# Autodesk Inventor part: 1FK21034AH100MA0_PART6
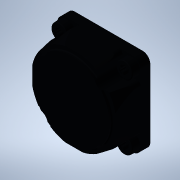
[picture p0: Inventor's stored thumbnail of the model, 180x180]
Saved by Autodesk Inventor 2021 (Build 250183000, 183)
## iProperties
Created: 2025-04
Part Number: 1FK21034AH100MA0_PART6
Material: Generic
Catalog Web Link: www.3dfindit.com
Description: -Servo synchronous motor
Document SubType Name: Modeling
Designer: psAdmin
Mass: 3.85693 g
Surface Area: 17.8404 cm^2
Volume: 3.85693 cm^3
Density: 1 g/cm^3
Appearance: PSOLRGB-48-56-69
Category: PARTsolutions
Title: 1FK21034AH100MA0_PART6
Author: Cadenas PARTsolutions
Comments: Servo synchronous motor
Sending System: PARTsolutions
Preprocessor: ST-DEVELOPER v19.3
PSOL_IDENT_0: {$CADENAS_DATA/23d-libs/siemens_ag/_cat_/39/97/1fk21034ah100ma0.prj},213 {VTYP=3D},{NB=1FK21034AH100
PSOL_IDENT_1: MA0_PART6},{LINA=1FK21034AH100MA0_PART6},{NN=1FK21034AH100MA0_PART6},{NOPRJ=TRUE},{DATE=19.08.2025 1
PSOL_IDENT_2: 4:00:33},{GEOMDATE=30.07.2025 02:02:21},{VERSION=},{LINEID=10},{WBVAR=},{WBNUMERIC=}  {NB=1FK21034AH
PSOL_IDENT_3: 100MA0_PART6},{LINA=1FK21034AH100MA0_PART6},{KT=DUMMY},{PREVIEW=../../../_pool_/d3/78/p_d211_xx_0093
PSOL_IDENT_4: 4j.png},{DESCSHORT=SIMOTICS S-1FK2 HD, SINAMICS S210 3AC 400V-480V, 1.01 Nm, 4500 rpm},{DESCLONG=SIM
PSOL_IDENT_5: OTICS S-1FK2 HD servo motor M0=1.27 Nm; PN = 0.48 kW at nN=4500 rpm (380-480 V); PN = 0.3 kW at nN=2
PSOL_IDENT_6: 500 rpm (200-240 V); with holding brake; degree of protection IP64; cylindrical shaft D14 x 30 mm; a
PSOL_IDENT_7: bsolute encoder 22-bit + 12-bit multiturn (encoder AM22DQC); with OCC interface; plug size M17, rota
PSOL_IDENT_8: table; SIMOTICS S-1FK2 servomotorfor a wide range of uses in industrial environments. SIMOTICS S‑1FK
PSOL_IDENT_9: 2 servomotors are compact synchronous motors with a high dynamic performance that set themselves apa
PSOL_IDENT_10: rt as a result of their high power density, degree of protection and overload capability. The motors
PSOL_IDENT_11: are available in two variants: as High Dynamic variant (highest dynamic performance as a result of
PSOL_IDENT_12: the low intrinsic moment of inertia for applications demanding a high dynamic performance with low m
PSOL_IDENT_13: oved masses) - and as Compact variant (precise and stable closed-loop control for medium up to large
PSOL_IDENT_14: moved masses as a result of a medium intrinsic moment of inertia). SIMOTICSS‑1FK2 servomotors fully
PSOL_IDENT_15: exploit their strengths in a system with the SINAMICSS210 frequency converter and simple connection
PSOL_IDENT_16: using the one cable connection (OCC). Advantages include the short control and positioning times, f
PSOL_IDENT_17: ast and precise correction of disturbing quantities as well as stable control with a high dynamic pe
PSOL_IDENT_18: rformance. The servo motors can be configured to address a wide range of requirements. For example w
PSOL_IDENT_19: ith and without holding brake, IP64 or IP65 degree of protection, singleturn or multiturn absolute e
PSOL_IDENT_20: ncoders - to name just a few. Further, the servomotors are available in different shaft heights exte
PSOL_IDENT_21: nding from 20 to 100. A shaft sealing ring is available to achieve an IP65 degree of protection and
PSOL_IDENT_22: for subsequent mounting at the motor or as spare part. SIMOTICS - the optimum motor for each and eve
PSOL_IDENT_23: ry motion control application.},{INTNO=195125454019},{SUPPLIERALTNO=1FK2103-4AH10-0MA0},{MANUID=1FK2
PSOL_IDENT_24: 1034AH100MA0},{MANUNAME=Siemens},{MANUTYPEDESC=SYNCHRONOUS MOTOR 1FK2 HD 1,27 NM},{AAU732=SIMOTICS},
PSOL_IDENT_25: {AAO057=S-1FK2},{AAU734=SIMOTICS S-1FK2 HD servo motor M0=1.27 Nm; PN = 0.48 kW at nN=4500 rpm (380-
PSOL_IDENT_26: 480 V); PN = 0.3 kW at nN=2500 rpm (200-240 V); with holding brake; degree of protection IP64; cylin
PSOL_IDENT_27: drical shaft D14 x 30 mm; absolute encoder 22-bit + 12-bit multiturn (encoder AM22DQC); with OCC int
PSOL_IDENT_28: erface; plug size M17, rotatable;},{AAW338=SYNCHRONOUS MOTOR 1FK2 HD 1,27 NM},{AAO742=SIMOTICS},{AAO
PSOL_IDENT_29: 663=4034106444921},{NOCUPEROU=1},{PRICEQUANTITY=1},{QUANTITYMIN=1},{QUANTITYINT=1},{CTN=85015100},{C
PSOL_IDENT_30: OO=RO},{AAO676=1FK2103-4AH10-0MA0},{AAO677=Siemens AG},{ORDERUNIT=C62},{CONTENTUNIT=C62}
NB: 1FK21034AH100MA0_PART6
NT: Servo synchronous motor
NBSYN: $MANUID._PART6
LINA: 1FK21034AH100MA0_PART6
CATALOG: SIEMENS
PREVIEW: ../../../_pool_/d3/78/p_d211_xx_00934j.png
DESCSHORT: SIMOTICS S-1FK2 HD, SINAMICS S210 3AC 400V-480V, 1.01 Nm, 4500 rpm
DESCLONG: SIMOTICS S-1FK2 HD servo motor M0=1.27 Nm; PN = 0.48 kW at nN=4500 rpm (380-480 V); PN = 0.3 kW at nN=2500 rpm (200-240 V); with holding brake; degree of protec
INTNO: 195125454019
SUPPLIERALTNO: 1FK2103-4AH10-0MA0
MANUID: 1FK21034AH100MA0
MANUNAME: Siemens
MANUTYPEDESC: SYNCHRONOUS MOTOR 1FK2 HD 1,27 NM
AAU732: SIMOTICS
AAO057: S-1FK2
AAU734: SIMOTICS S-1FK2 HD servo motor M0=1.27 Nm; PN = 0.48 kW at nN=4500 rpm (380-480 V); PN = 0.3 kW at nN=2500 rpm (200-240 V); with holding brake; degree of protec
AAW338: SYNCHRONOUS MOTOR 1FK2 HD 1,27 NM
AAO742: SIMOTICS
AAO663: 4034106444921.0
NOCUPEROU: 1
PRICEQUANTITY: 1
QUANTITYMIN: 1
QUANTITYINT: 1
CTN: 85015100
COO: RO
ARTICLENO: 1FK21034AH100MA0_PART6
BOMINFO: 1FK21034AH100MA0_PART6
CREATOR: CADENAS GmbH
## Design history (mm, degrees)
feature "2025_04_17_15_09_00_0299"
body "Solid1"
